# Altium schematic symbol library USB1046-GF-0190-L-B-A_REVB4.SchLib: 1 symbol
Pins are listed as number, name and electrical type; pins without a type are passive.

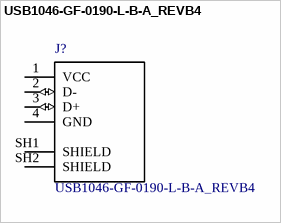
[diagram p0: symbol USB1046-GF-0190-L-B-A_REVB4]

## USB1046-GF-0190-L-B-A_REVB4
designator J?
USB-A (USB TYPE-A) USB 2.0 Receptacle Connector 4 Position Surface Mount, Through Hole; MF: Global Connector Technology
footprint *GCT_USB1046-GF-0190-L-B-A_REVB4_USB1046-GF-0190-L-B-A_REVB4(Primary)
pins: 1 VCC (power), 2 D- (io), 3 D+ (io), 4 GND (power), SH1 SHIELD, SH2 SHIELD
